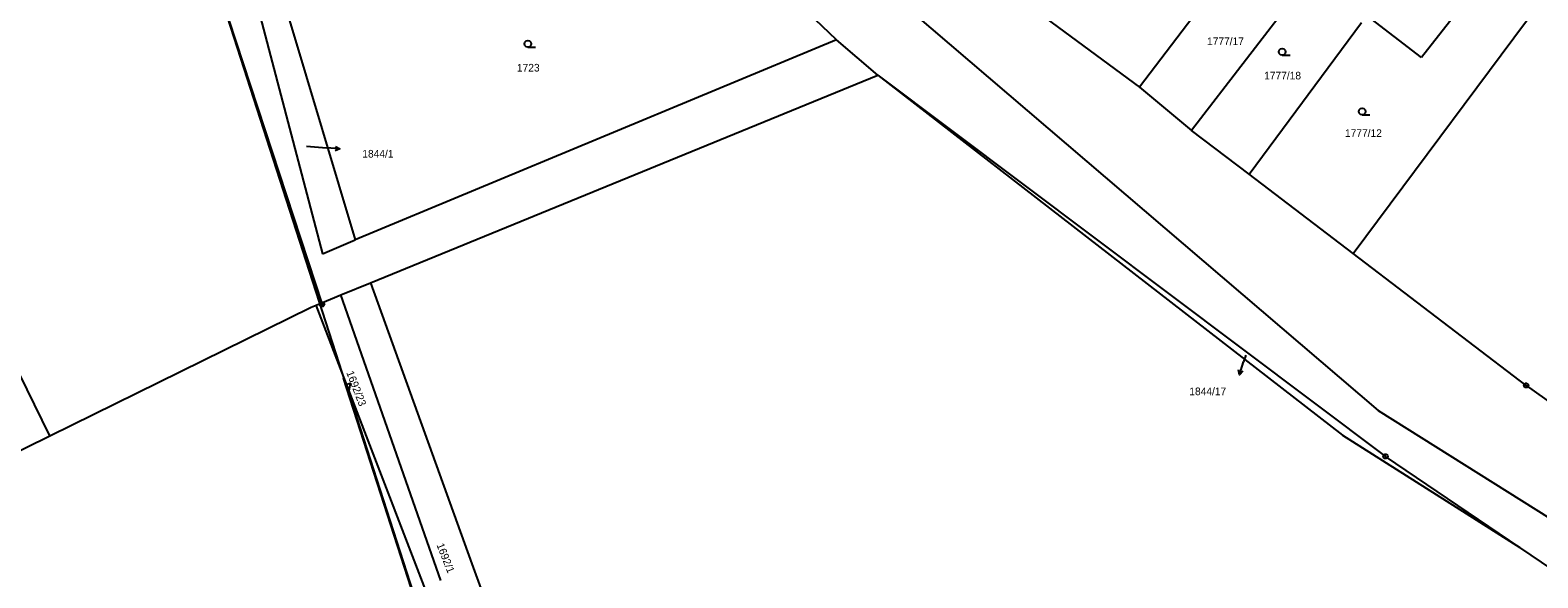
# Model space of a CAD drawing. Extents: x -747792 to -745414, y -1093712 to -1091463.
# Drawn here: x -747029.6 to -746861.7, y -1092335.2 to -1092274.2 of the extents above; entities that cross this region are included whole.
import ezdxf

# ---------------------------------------------------------------- set-up
doc = ezdxf.new("R2010")
doc.units = 0
for name, color, linetype in [('Pracovní_bod JDTM STC_VC', 7, 'Continuous'), ('Pracovní_bod JDTM STC_VC - číslo', 7, 'Continuous'), ('Pracovní_bod NN - výška', 7, 'Continuous'), ('Pracovní_bod polohopisu - výška', 7, 'Continuous'), ('Pracovní_bod polohopisu - číslo', 7, 'Continuous'), ('Pracovní_bod VN - výška', 7, 'Continuous')]:
    doc.layers.add(name, color=color, linetype=linetype)

msp = doc.modelspace()

# ---------------------------------------------------------------- linework, layer by layer
at = {"layer": 'Pracovní_bod JDTM STC_VC - číslo'}
for points in [[(-746974.19, -1092276.1), (-746974.38, -1092276.05), (-746974.51, -1092275.91), (-746974.57, -1092275.73), (-746974.51, -1092275.54), (-746974.38, -1092275.4), (-746974.19, -1092275.35), (-746974, -1092275.4), (-746973.86, -1092275.54), (-746973.82, -1092275.73), (-746973.86, -1092275.91), (-746974, -1092276.05), (-746974.19, -1092276.1), (-746973.32, -1092276.1)], [(-746890.2, -1092276.98), (-746890.39, -1092276.93), (-746890.52, -1092276.79), (-746890.58, -1092276.6), (-746890.52, -1092276.42), (-746890.39, -1092276.28), (-746890.2, -1092276.23), (-746890.01, -1092276.28), (-746889.88, -1092276.42), (-746889.83, -1092276.6), (-746889.88, -1092276.79), (-746890.01, -1092276.93), (-746890.2, -1092276.98), (-746889.33, -1092276.98)], [(-746881.3, -1092283.62), (-746881.49, -1092283.57), (-746881.62, -1092283.43), (-746881.68, -1092283.25), (-746881.62, -1092283.06), (-746881.49, -1092282.92), (-746881.3, -1092282.87), (-746881.11, -1092282.92), (-746880.98, -1092283.06), (-746880.93, -1092283.25), (-746880.98, -1092283.43), (-746881.11, -1092283.57), (-746881.3, -1092283.62), (-746880.43, -1092283.62)]]:
    msp.add_lwpolyline(points, dxfattribs=at)
at = {"layer": 'Pracovní_bod NN - výška'}
for points in [[(-746946.7, -1092259.07), (-746879.52, -1092316.53)], [(-746939.81, -1092275.27), (-746953.13, -1092262.55)], [(-746894.7, -1092265.54), (-746906.07, -1092280.56)], [(-747005.34, -1092267.41), (-746997.05, -1092299.1)], [(-746868.3, -1092269.09), (-746874.7, -1092277.24)], [(-746888.05, -1092269.46), (-746900.3, -1092285.35)], [(-746882.31, -1092299.06), (-746860.28, -1092269.48)], [(-746917.94, -1092271.82), (-746906.07, -1092280.56)], [(-746874.7, -1092277.24), (-746880.76, -1092272.57)], [(-747000.7, -1092273.13), (-746993.42, -1092297.55)], [(-746893.89, -1092290.23), (-746881.38, -1092273.33)], [(-746939.81, -1092275.27), (-746993.42, -1092297.55)], [(-746935.22, -1092279.2), (-746939.81, -1092275.27)], [(-746991.69, -1092302.32), (-746935.22, -1092279.2)], [(-746935.22, -1092279.2), (-746878.69, -1092321.66)], [(-746935.22, -1092279.2), (-746883.48, -1092319.3)], [(-746906.07, -1092280.56), (-746900.3, -1092285.35)], [(-746893.89, -1092290.23), (-746900.3, -1092285.35)], [(-747027.4, -1092319.35), (-747043.49, -1092286.5)], [(-746882.31, -1092299.06), (-746893.89, -1092290.23)], [(-746997.05, -1092299.1), (-746993.42, -1092297.55)], [(-746863.04, -1092313.75), (-746882.31, -1092299.06)], [(-746995.01, -1092303.68), (-746991.69, -1092302.32)], [(-746991.69, -1092302.32), (-746980.43, -1092333.62)], [(-746997.75, -1092304.8), (-746995.01, -1092303.68)], [(-746983.86, -1092335.49), (-746995.01, -1092303.68)], [(-747027.4, -1092319.35), (-746998.31, -1092305.03)], [(-746998.31, -1092305.03), (-746997.75, -1092304.8)], [(-746983.77, -1092341.24), (-746997.75, -1092304.8)], [(-746863.04, -1092313.75), (-746801.85, -1092357.16)], [(-746879.52, -1092316.53), (-746809.3, -1092360.63)], [(-747058.92, -1092334.87), (-747027.4, -1092319.35)], [(-746883.48, -1092319.3), (-746863.74, -1092331.79)], [(-746863.74, -1092331.79), (-746878.69, -1092321.66)], [(-746812.98, -1092366.18), (-746863.74, -1092331.79)], [(-746980.43, -1092333.62), (-746967.73, -1092368.43)]]:
    msp.add_lwpolyline(points, dxfattribs=at)
at = {"layer": 'Pracovní_bod polohopisu - výška'}
for points in [[(-746998.84, -1092287.12), (-746996.6, -1092287.3)], [(-746995.1, -1092287.42), (-746996.6, -1092287.3)], [(-746995.58, -1092287.13), (-746995.1, -1092287.42), (-746995.62, -1092287.63)], [(-746894.97, -1092312.56), (-746894.5, -1092311.14)], [(-746894.26, -1092310.4), (-746894.5, -1092311.14)], [(-746894.57, -1092312.17), (-746894.97, -1092312.56), (-746895.05, -1092312.01)]]:
    msp.add_lwpolyline(points, dxfattribs=at)
at = {"layer": 'Pracovní_bod polohopisu - číslo'}
for points in [[(-747025.09, -1092219.35), (-746997.09, -1092304.73), (-747011.64, -1092260.38)], [(-747010.55, -1092263.7), (-746977.75, -1092365.49), (-746994.69, -1092312.93)], [(-746997.17, -1092304.49), (-746997.01, -1092304.49), (-746996.89, -1092304.58), (-746996.83, -1092304.73), (-746996.89, -1092304.87), (-746997.01, -1092304.96), (-746997.17, -1092304.96), (-746997.29, -1092304.87), (-746997.34, -1092304.73), (-746997.29, -1092304.58), (-746997.17, -1092304.49), (-746997.15, -1092304.51), (-746997.03, -1092304.51), (-746996.95, -1092304.55), (-746997.23, -1092304.55), (-746997.27, -1092304.59), (-746996.91, -1092304.59), (-746996.91, -1092304.63), (-746997.27, -1092304.63), (-746997.29, -1092304.67), (-746996.89, -1092304.67), (-746996.87, -1092304.71), (-746997.31, -1092304.71), (-746997.31, -1092304.75), (-746996.87, -1092304.75), (-746996.89, -1092304.79), (-746997.29, -1092304.79), (-746997.28, -1092304.83), (-746996.88, -1092304.83), (-746996.91, -1092304.87), (-746997.26, -1092304.87), (-746997.22, -1092304.91), (-746996.95, -1092304.91), (-746997, -1092304.95), (-746997.17, -1092304.95)], [(-746994.61, -1092313.17), (-746994.46, -1092313.64), (-746993.98, -1092313.49), (-746994.15, -1092314.6), (-746993.69, -1092316.02)], [(-746993.61, -1092316.26), (-746958.63, -1092424.66), (-746976.66, -1092368.8)]]:
    msp.add_lwpolyline(points, dxfattribs=at)
at = {"layer": 'Pracovní_bod VN - výška'}
for points in [[(-746862.97, -1092313.51), (-746862.84, -1092313.6), (-746862.79, -1092313.75), (-746862.84, -1092313.9), (-746862.97, -1092313.99), (-746863.11, -1092313.99), (-746863.24, -1092313.9), (-746863.29, -1092313.75), (-746863.24, -1092313.6), (-746863.11, -1092313.51)], [(-746878.61, -1092321.42), (-746878.49, -1092321.52), (-746878.44, -1092321.66), (-746878.49, -1092321.8), (-746878.61, -1092321.9), (-746878.76, -1092321.9), (-746878.89, -1092321.8), (-746878.94, -1092321.66), (-746878.89, -1092321.52), (-746878.76, -1092321.42)]]:
    msp.add_lwpolyline(points, close=True, dxfattribs=at)
for points in [[(-746863.07, -1092313.75), (-746863.02, -1092313.75)], [(-746878.71, -1092321.66), (-746878.66, -1092321.66)]]:
    msp.add_lwpolyline(points, dxfattribs=at)

# ---------------------------------------------------------------- texts
at = {"layer": 'Pracovní_bod JDTM STC_VC'}
for s, height, p in [('1777/17', 0.85, (-746898.57, -1092275.86)), ('1723', 0.85, (-746975.4, -1092278.8)), ('1777/18', 0.85, (-746892.21, -1092279.68)), ('1777/12', 0.85, (-746883.21, -1092286.08)), ('1844/1', 0.05, (-746998.94, -1092287.12)), ('1844/17', 0.05, (-746894.38, -1092310.4))]:
    msp.add_text(s, height=height, dxfattribs=at).set_placement(p)
for s, rotation, p in [('1692/23', 291.1199, (-746994.41, -1092312.32)), ('1692/1', 291.6355, (-746984.37, -1092331.51))]:
    msp.add_text(s, height=0.85, rotation=rotation, dxfattribs=at).set_placement(p)
at = {"layer": 'Pracovní_bod polohopisu - výška'}
for s, p in [('1844/1', (-746992.61, -1092288.38)), ('1844/17', (-746900.54, -1092314.84))]:
    msp.add_text(s, height=0.85, dxfattribs=at).set_placement(p)

doc.saveas('drawing.dxf')
